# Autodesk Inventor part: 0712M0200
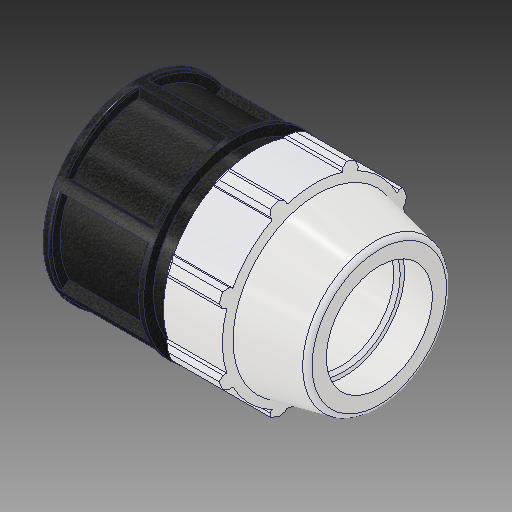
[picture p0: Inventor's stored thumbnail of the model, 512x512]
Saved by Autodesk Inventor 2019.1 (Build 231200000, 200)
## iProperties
Created: 2017-02
Part Number: 0712M0200
Material: PVC-Piping
Description: PLASSON END PLUG 2''
Document SubType Name: Modeling
Designer: KIM
Mass: 92.6774 g
Surface Area: 199.44 cm^2
Volume: 66.1981 cm^3
Density: 1.4 g/cm^3
Appearance: PTFE
Author: Кирилл
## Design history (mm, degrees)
derived "0712M0.ipt"
feature "Solid1::0712M0.ipt"
tag "TaggingFeature1"
body "Solid1"
other parameters: "d2" = 60.1, "d4" = 19.99343, "d5" = 34.9885, "d7" = 113.03, "d8" = 96.0755, "d9" = 19.99343, "d11" = 3.99869, "d12" = 96.0755, "d13" = 120 deg, "d15" = 12 deg, "d16" = 107.3785, "d18" = 3.005, "d19" = 35 deg, "d20" = 17.5 deg, "d21" = 105.1179, "d23" = 0, "d25" = 360 deg, "d27" = 2.2606, "d34" = 5.6515, "d36" = 0, "d42" = 34.9885, "d43" = 3.3909, "d46" = 1.803, "d53" = 1.202, "d55" = 360 deg, "d59" = 48.9839, "d64" = 139.954, "d66" = 11.303, "d67" = 5.6515, "d68" = 133.096, "d70" = 96.0755, "d_" = 60.1, "E_" = 113.03, "H_" = 139.954, "l_" = 133.096
